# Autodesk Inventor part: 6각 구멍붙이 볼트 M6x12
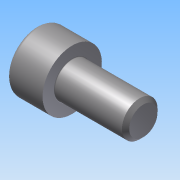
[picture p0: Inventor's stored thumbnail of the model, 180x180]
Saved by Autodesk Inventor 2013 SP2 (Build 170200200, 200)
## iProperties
Created: 2025-06
Part Number: 6각 구멍붙이 볼트 M6x12
Material: Generic
Document SubType Name: Modeling
Designer: a
Density: 1 g/cm^3
Author: a
변환 표준: STEP AP214IS
전처리기: Build: 200, Release: 2013 SP2 Update 6 - Date: Thu 07/17/2014
전송 단위: 밀리미터
불확실성: 0.01
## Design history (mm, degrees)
node "6각 구멍붙이 볼트 M6x121"
body "Solid1"
node "기준1"
